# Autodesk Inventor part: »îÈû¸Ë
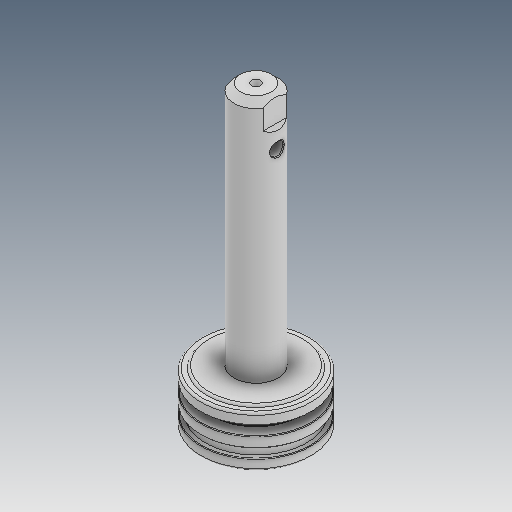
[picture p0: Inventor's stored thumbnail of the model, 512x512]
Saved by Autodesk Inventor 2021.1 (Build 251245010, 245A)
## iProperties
Created: 2014-12
Part Number: »îÈû¸Ë
Material: Ogólny
Document SubType Name: Modeling
Designer: user
Density: 1 g/cm^3
Appearance: Domyślna
Author: user
Revision Number: ÈÎºÎ
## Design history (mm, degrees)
feature "ÊäÈë1"
node "Bryła1"
